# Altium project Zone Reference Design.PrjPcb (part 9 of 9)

## Sheet Class-D Amp.SchDoc
size 431 x 279 mm; Date: Not shown in title block; ApprovedBy: Not shown in title block; CheckedBy: Not shown in title block; Author: Not shown in title block; CompanyName: Not shown in title block; Engineer: Not shown in title block; Organization: Not shown in title block; Address1: Not shown in title block; Address2: Not shown in title block; Address3: Not shown in title block; Address4: Not shown in title block; DocumentNumber: 1; Revision: Use project parameter SCH_Rev; SheetNumber: 25; SheetTotal: 30; PageSetup: Record=PageOptions¦CenterHorizontal=True¦CenterVertical=True¦PrintScale=1.00¦XCorrection=1.00¦YCorrection=1.00¦PrintKind=0¦BorderSize=5000000¦LeftOffset=0¦BottomOffset=0¦Orientation=2¦PaperLength=1000¦PaperWidth=1000¦Scale=100¦PaperSource=15¦PrintQuality=600¦MediaType=1¦DitherType=10¦PaperKind=Letter¦PrintScaleMode=1
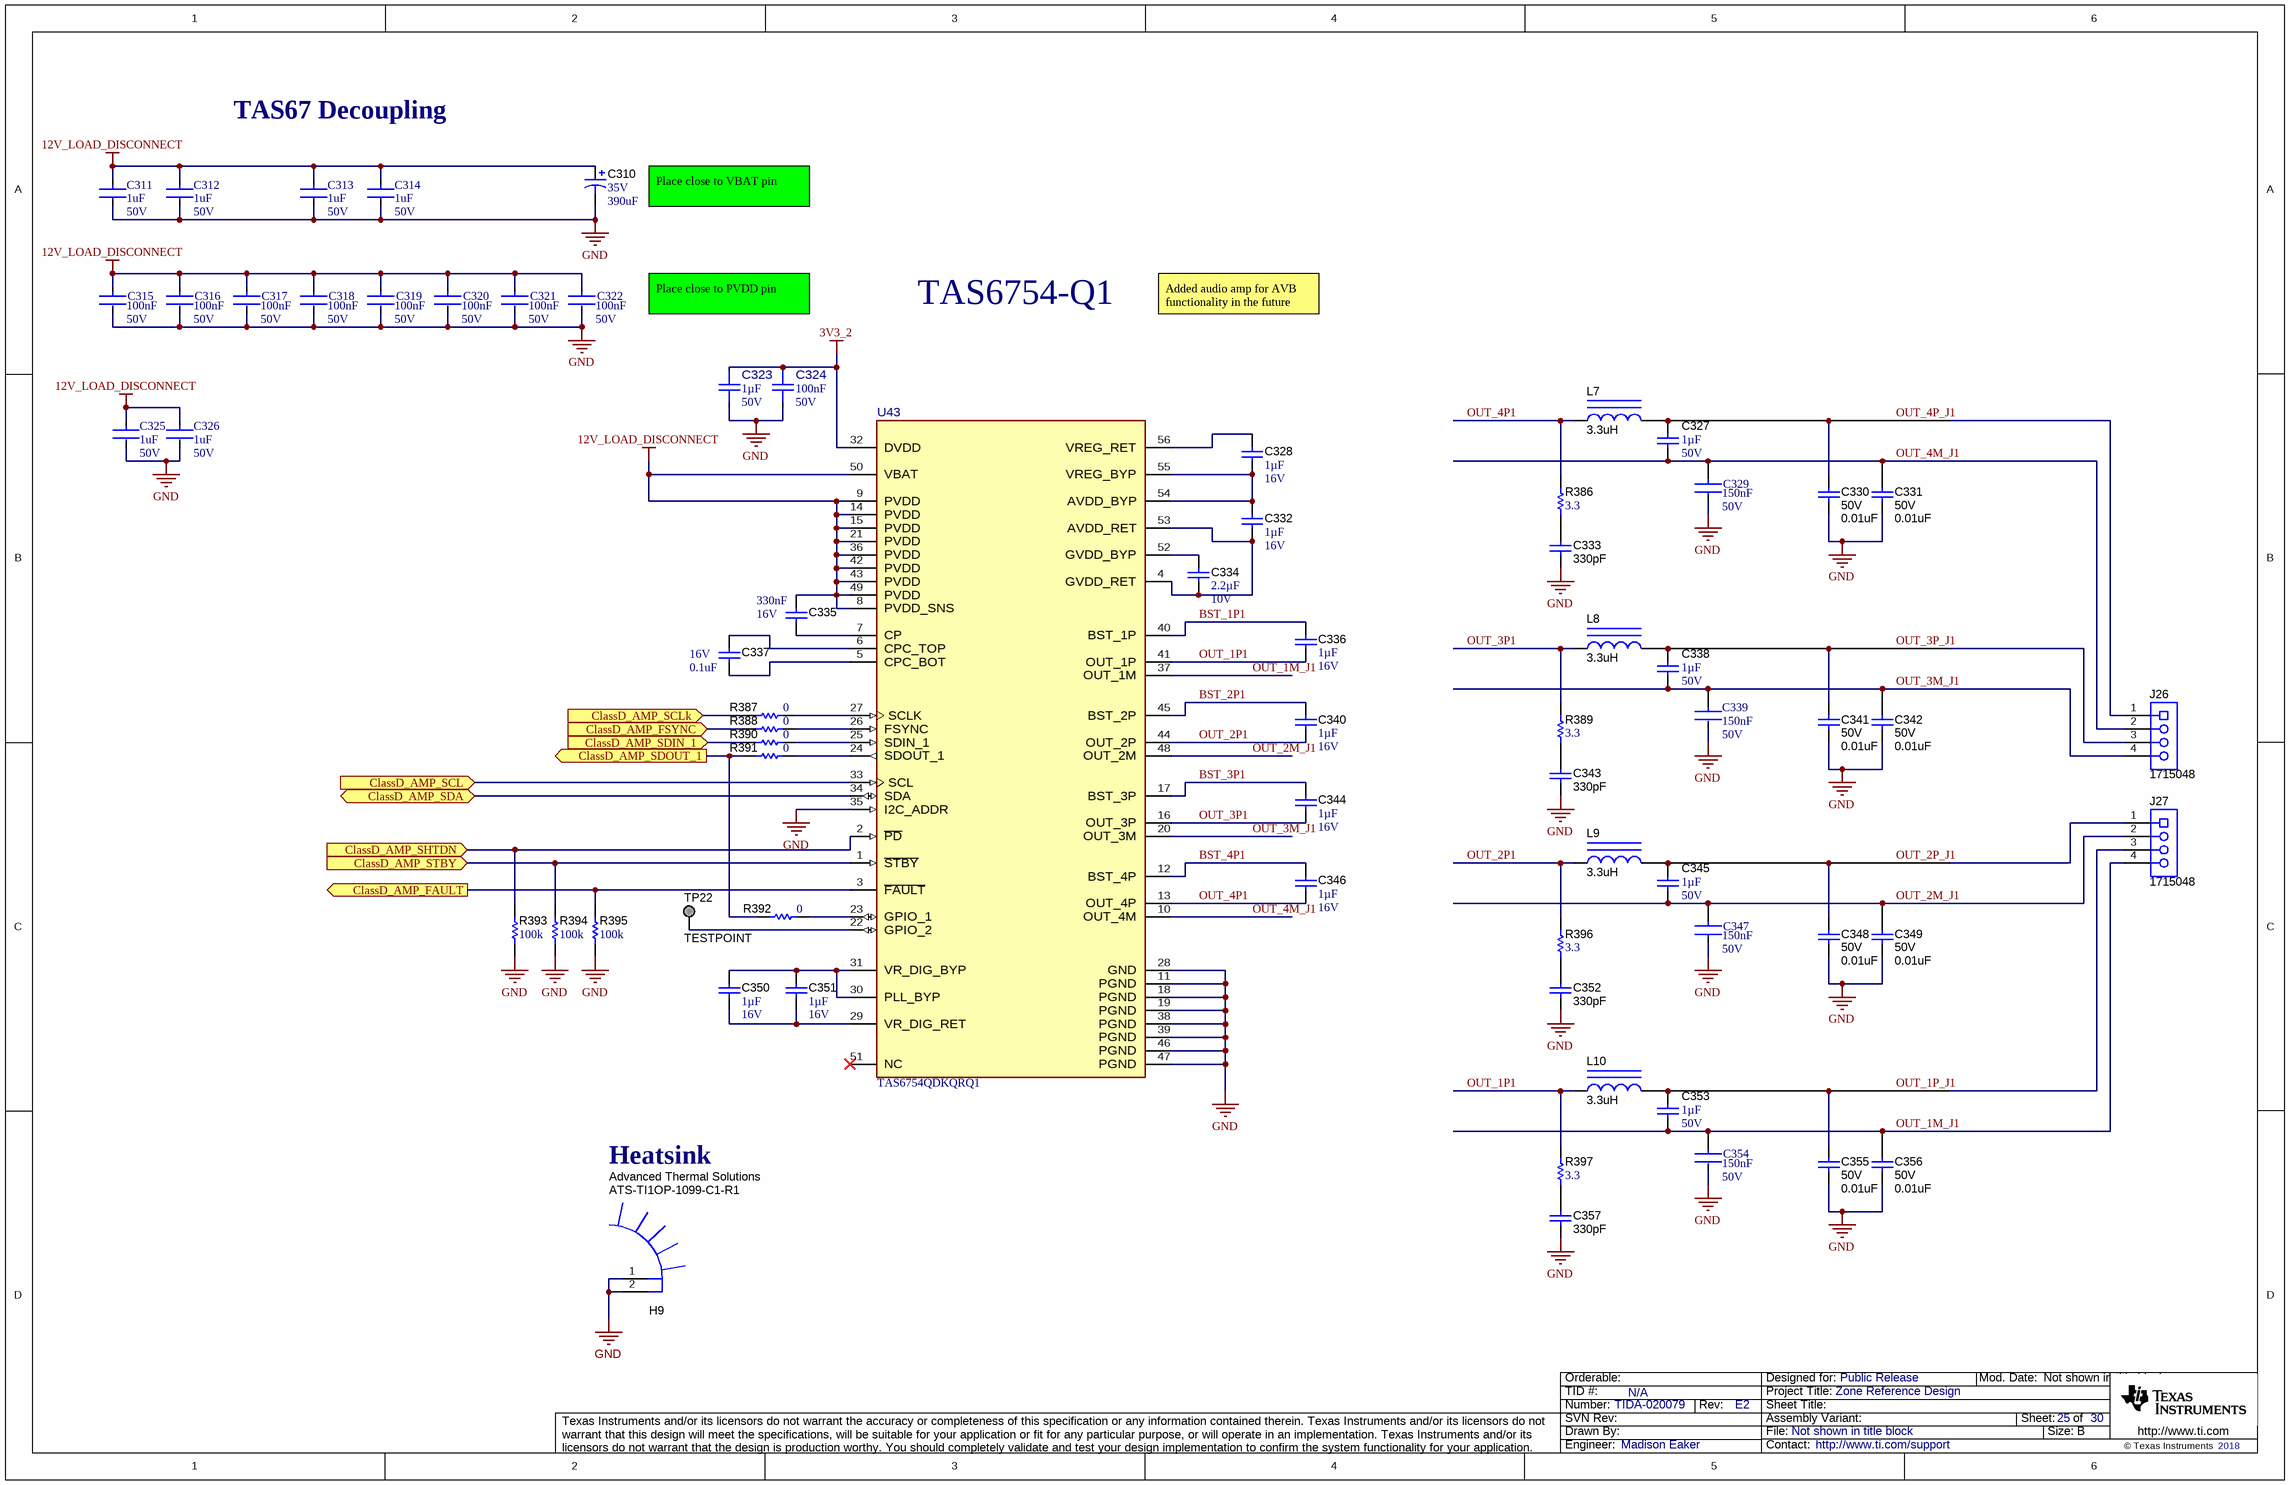
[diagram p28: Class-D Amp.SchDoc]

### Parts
C310  VDC_V: 35V  ValueDisplayed: 390uF  [SM_RADIAL_10BMM]  (hidden comment: UCL1V391MNL1GS)
C311  Voltage Rating: 50V  Capacitance: 1uF  [FP-GCJ21B-0_3-IPC_A]  (hidden comment: GCJ21BR71H105MA01L)
C312  Voltage Rating: 50V  Capacitance: 1uF  [FP-GCJ21B-0_3-IPC_A]  (hidden comment: GCJ21BR71H105MA01L)
C313  Voltage Rating: 50V  Capacitance: 1uF  [FP-GCJ21B-0_3-IPC_A]  (hidden comment: GCJ21BR71H105MA01L)
C314  Voltage Rating: 50V  Capacitance: 1uF  [FP-GCJ21B-0_3-IPC_A]  (hidden comment: GCJ21BR71H105MA01L)
C315  Voltage Rating (DC): 50V  Capacitance: 100nF  [FP-GCJ188-0_2-IPC_C]  (hidden comment: GCJ188R71H104KA12D)
C316  Voltage Rating (DC): 50V  Capacitance: 100nF  [FP-GCJ188-0_2-IPC_C]  (hidden comment: GCJ188R71H104KA12D)
C317  Voltage Rating (DC): 50V  Capacitance: 100nF  [FP-GCJ188-0_2-IPC_C]  (hidden comment: GCJ188R71H104KA12D)
C318  Voltage Rating (DC): 50V  Capacitance: 100nF  [FP-GCJ188-0_2-IPC_C]  (hidden comment: GCJ188R71H104KA12D)
C319  Voltage Rating (DC): 50V  Capacitance: 100nF  [FP-GCJ188-0_2-IPC_C]  (hidden comment: GCJ188R71H104KA12D)
C320  Voltage Rating (DC): 50V  Capacitance: 100nF  [FP-GCJ188-0_2-IPC_C]  (hidden comment: GCJ188R71H104KA12D)
C321  Voltage Rating (DC): 50V  Capacitance: 100nF  [FP-GCJ188-0_2-IPC_C]  (hidden comment: GCJ188R71H104KA12D)
C322  Voltage Rating (DC): 50V  Capacitance: 100nF  [FP-GCJ188-0_2-IPC_C]  (hidden comment: GCJ188R71H104KA12D)
C323  Cap_F: 1µF  VDC_V: 50V  [FP-CL10B105KB9VPJC_0603-MFG]  (hidden comment: CL10B105KB9VPJC)
C324  Cap_F: 100nF  VDC_V: 50V  [FP-C0603X104K5RACAUTO_0603-MFG]  (hidden comment: C0603X104K5RACAUTO)
C325  Voltage Rating: 50V  Capacitance: 1uF  [FP-GCJ21B-0_3-IPC_A]  (hidden comment: GCJ21BR71H105MA01L)
C326  Voltage Rating: 50V  Capacitance: 1uF  [FP-GCJ21B-0_3-IPC_A]  (hidden comment: GCJ21BR71H105MA01L)
C327  Cap_F: 1µF  VDC_V: 50V  [0805_HV]  (hidden comment: GCM21BR71H105KA03K)
C328  Cap_F: 1µF  VDC_V: 16V  [0603]  (hidden comment: GCM188R71C105KA64J)
C329  Voltage Rating: 50V  Capacitance: 150nF  [FP-GCM188-0_1-IPC_C]  (hidden comment: GCM188R71H154KA64D)
C330  VDC_V: 50V  ValueDisplayed: 0.01uF  [0603]  (hidden comment: GRM1885C1H103JA01D)
C331  VDC_V: 50V  ValueDisplayed: 0.01uF  [0603]  (hidden comment: GRM1885C1H103JA01D)
C332  Cap_F: 1µF  VDC_V: 16V  [0603]  (hidden comment: GCM188R71C105KA64J)
C333  ValueDisplayed: 330pF  [0402]  (hidden comment: GRM155R71H331KA01D)
C334  Cap_F: 2.2µF  VDC_V: 10V  [0603]  (hidden comment: GRM188R71A225KE15J)
C335  Cap_F: 330nF  VDC_V: 16V  [0603]  (hidden comment: GRM188R71C334KA01D)
C336  Cap_F: 1µF  VDC_V: 16V  [0603]  (hidden comment: GCM188R71C105KA64D)
C337  VDC_V: 16V  ValueDisplayed: 0.1uF  [0402]  (hidden comment: GCM155R71C104KA55D)
C338  Cap_F: 1µF  VDC_V: 50V  [0805_HV]  (hidden comment: GCM21BR71H105KA03K)
C339  Voltage Rating: 50V  Capacitance: 150nF  [FP-GCM188-0_1-IPC_C]  (hidden comment: GCM188R71H154KA64D)
C340  Cap_F: 1µF  VDC_V: 16V  [0603]  (hidden comment: GCM188R71C105KA64D)
C341  VDC_V: 50V  ValueDisplayed: 0.01uF  [0603]  (hidden comment: GRM1885C1H103JA01D)
C342  VDC_V: 50V  ValueDisplayed: 0.01uF  [0603]  (hidden comment: GRM1885C1H103JA01D)
C343  ValueDisplayed: 330pF  [0402]  (hidden comment: GRM155R71H331KA01D)
C344  Cap_F: 1µF  VDC_V: 16V  [0603]  (hidden comment: GCM188R71C105KA64D)
C345  Cap_F: 1µF  VDC_V: 50V  [0805_HV]  (hidden comment: GCM21BR71H105KA03K)
C346  Cap_F: 1µF  VDC_V: 16V  [0603]  (hidden comment: GCM188R71C105KA64D)
C347  Voltage Rating: 50V  Capacitance: 150nF  [FP-GCM188-0_1-IPC_C]  (hidden comment: GCM188R71H154KA64D)
C348  VDC_V: 50V  ValueDisplayed: 0.01uF  [0603]  (hidden comment: GRM1885C1H103JA01D)
C349  VDC_V: 50V  ValueDisplayed: 0.01uF  [0603]  (hidden comment: GRM1885C1H103JA01D)
C350  Cap_F: 1µF  VDC_V: 16V  [0603]  (hidden comment: GCM188R71C105KA64J)
C351  Cap_F: 1µF  VDC_V: 16V  [0603]  (hidden comment: GCM188R71C105KA64J)
C352  ValueDisplayed: 330pF  [0402]  (hidden comment: GRM155R71H331KA01D)
C353  Cap_F: 1µF  VDC_V: 50V  [0805_HV]  (hidden comment: GCM21BR71H105KA03K)
C354  Voltage Rating: 50V  Capacitance: 150nF  [FP-GCM188-0_1-IPC_C]  (hidden comment: GCM188R71H154KA64D)
C355  VDC_V: 50V  ValueDisplayed: 0.01uF  [0603]  (hidden comment: GRM1885C1H103JA01D)
C356  VDC_V: 50V  ValueDisplayed: 0.01uF  [0603]  (hidden comment: GRM1885C1H103JA01D)
C357  ValueDisplayed: 330pF  [0402]  (hidden comment: GRM155R71H331KA01D)
H9  Manufacturer: Advanced Thermal Solutions  PartNumber: ATS-TI1OP-1099-C1-R1  [HEATSINK-DKQ56_20MMX41_4X32_77MM]  (hidden comment: HeatSink_2)
J26  1715048  [Phoenix_1715048]
J27  1715048  [Phoenix_1715048]
L7  ValueDisplayed: 3.3uH  [VCMT053T]  (hidden comment: VCMT053T-3R3MN5)
L8  ValueDisplayed: 3.3uH  [VCMT053T]  (hidden comment: VCMT053T-3R3MN5)
L9  ValueDisplayed: 3.3uH  [VCMT053T]  (hidden comment: VCMT053T-3R3MN5)
L10  ValueDisplayed: 3.3uH  [VCMT053T]  (hidden comment: VCMT053T-3R3MN5)
R386  ValueDisplayed: 3.3  [0603]  (hidden comment: CRCW06033R30JNEA)
R387  ValueDisplayed: 0  [0603]  (hidden comment: RC0603JR-070RL)
R388  ValueDisplayed: 0  [0603]  (hidden comment: RC0603JR-070RL)
R389  ValueDisplayed: 3.3  [0603]  (hidden comment: CRCW06033R30JNEA)
R390  ValueDisplayed: 0  [0603]  (hidden comment: RC0603JR-070RL)
R391  ValueDisplayed: 0  [0603]  (hidden comment: RC0603JR-070RL)
R392  ValueDisplayed: 0  [0603]  (hidden comment: RC0603JR-070RL)
R393  ValueDisplayed: 100k  [0603]  (hidden comment: CRCW0603100KJNEAC)
R394  ValueDisplayed: 100k  [0603]  (hidden comment: CRCW0603100KJNEAC)
R395  ValueDisplayed: 100k  [0603]  (hidden comment: CRCW0603100KJNEAC)
R396  ValueDisplayed: 3.3  [0603]  (hidden comment: CRCW06033R30JNEA)
R397  ValueDisplayed: 3.3  [0603]  (hidden comment: CRCW06033R30JNEA)
TP22  TESTPOINT  [TP_25MIL-SMT]  (no BOM)
U43  TAS6754QDKQRQ1  [DKQ0056D-MFG]

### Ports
ClassD_AMP_FAULT (out), ClassD_AMP_FSYNC (in), ClassD_AMP_SCL (in), ClassD_AMP_SCLk (in), ClassD_AMP_SDA (bidir), ClassD_AMP_SDIN_1 (in), ClassD_AMP_SDOUT_1 (out), ClassD_AMP_SHTDN (in), ClassD_AMP_STBY (in)

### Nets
3V3_2: C323.1 C324.1 U43.32(DVDD)
12V_LOAD_DISCONNECT: C310.1(+) C311.1 C312.1 C313.1 C314.1 C315.2 C316.2 C317.2 C318.2 C319.2 C320.2 C321.2 C322.2 C325.1 C326.1 C335.2 U43.8(PVDD_SNS) U43.9(PVDD) U43.14(PVDD) U43.15(PVDD) U43.21(PVDD) U43.36(PVDD) U43.42(PVDD) U43.43(PVDD) U43.49(PVDD) U43.50(VBAT)  [project net VS]
GND: C310.2(-) C311.2 C312.2 C313.2 C314.2 C315.1 C316.1 C317.1 C318.1 C319.1 C320.1 C321.1 C322.1 C323.2 C324.2 C325.2 C326.2 C329.2 C330.2 C331.2 C333.1 C339.2 C341.2 C342.2 C343.1 C347.2 C348.2 C349.2 C352.1 C354.2 C355.2 C356.2 C357.1 H9.1 H9.2 R393.2 R394.2 R395.2 U43.11(PGND) U43.18(PGND) U43.19(PGND) U43.28(GND) U43.35(I2C_ADDR) U43.38(PGND) U43.39(PGND) U43.46(PGND) U43.47(PGND)
BST_1P1: C336.2 U43.40(BST_1P)  [project net BST_1P1_25]
BST_2P1: C340.2 U43.45(BST_2P)  [project net BST_2P1_25]
BST_3P1: C344.2 U43.17(BST_3P)  [project net BST_3P1_25]
BST_4P1: C346.2 U43.12(BST_4P)  [project net BST_4P1_25]
ClassD_AMP_FAULT: R395.1 U43.3(~{FAULT}) ; port ClassD_AMP_FAULT
ClassD_AMP_FSYNC: R388.1 ; port ClassD_AMP_FSYNC
ClassD_AMP_SCLk: R387.1 ; port ClassD_AMP_SCLk
ClassD_AMP_SDIN_1: R390.1 ; port ClassD_AMP_SDIN_1
ClassD_AMP_SDOUT_1: R391.1 R392.1 ; port ClassD_AMP_SDOUT_1
ClassD_AMP_SHTDN: R393.1 U43.2(~{PD}) ; port ClassD_AMP_SHTDN
ClassD_AMP_STBY: R394.1 U43.1(~{STBY}) ; port ClassD_AMP_STBY
I2C0_SCL: U43.33(SCL) ; port ClassD_AMP_SCL
I2C0_SDA: U43.34(SDA) ; port ClassD_AMP_SDA
OUT_1M_J1: C353.2 C354.1 C356.1 J27.4 U43.37(OUT_1M)  [project net OUT_1M_J1_25]
OUT_1P1: C336.1 L10.1 R397.2 U43.41(OUT_1P)  [project net OUT_1P1_25]
OUT_1P_J1: C353.1 C355.1 J27.3 L10.2  [project net OUT_1P_J1_25]
OUT_2M_J1: C345.2 C347.1 C349.1 J27.2 U43.48(OUT_2M)  [project net OUT_2M_J1_25]
OUT_2P1: C340.1 L9.1 R396.2 U43.44(OUT_2P)  [project net OUT_2P1_25]
OUT_2P_J1: C345.1 C348.1 J27.1 L9.2  [project net OUT_2P_J1_25]
OUT_3M_J1: C338.2 C339.1 C342.1 J26.4 U43.20(OUT_3M)  [project net OUT_3M_J1_25]
OUT_3P1: C344.1 L8.1 R389.2 U43.16(OUT_3P)  [project net OUT_3P1_25]
OUT_3P_J1: C338.1 C341.1 J26.3 L8.2  [project net OUT_3P_J1_25]
OUT_4M_J1: C327.2 C329.1 C331.1 J26.2 U43.10(OUT_4M)  [project net OUT_4M_J1_25]
OUT_4P1: C346.1 L7.1 R386.2 U43.13(OUT_4P)  [project net OUT_4P1_25]
OUT_4P_J1: C327.1 C330.1 J26.1 L7.2  [project net OUT_4P_J1_25]
NetC328_1: C328.1 C332.2 U43.54(AVDD_BYP) U43.55(VREG_BYP)
NetC328_2: C328.2 U43.56(VREG_RET)
NetC332_1: C332.1 C334.1 U43.4(GVDD_RET) U43.53(AVDD_RET)
NetC333_2: C333.2 R386.1
NetC334_2: C334.2 U43.52(GVDD_BYP)
NetC335_1: C335.1 U43.7(CP)
NetC337_1: C337.1 U43.6(CPC_TOP)
NetC337_2: C337.2 U43.5(CPC_BOT)
NetC343_2: C343.2 R389.1
NetC350_1: C350.1 C351.1 U43.29(VR_DIG_RET)
NetC350_2: C350.2 C351.2 U43.30(PLL_BYP) U43.31(VR_DIG_BYP)
NetC352_2: C352.2 R396.1
NetC357_2: C357.2 R397.1
NetR387_2: R387.2 U43.27(SCLK)
NetR388_2: R388.2 U43.26(FSYNC)
NetR390_2: R390.2 U43.25(SDIN_1)
NetR391_2: R391.2 U43.24(SDOUT_1)
NetR392_2: R392.2 U43.23(GPIO_1)
NetTP22_1: TP22.1 U43.22(GPIO_2)

Not connected (* = marked no-connect by the designer): U43 51(NC)*

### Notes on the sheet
- TAS67 Decoupling
- Place close to VBAT pin
- Place close to PVDD pin
- TAS6754-Q1
- Added audio amp for AVB functionality in the future
- Heatsink

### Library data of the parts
C310 = CMP-0011092-1: CAP, AL, 390 uF, 35 V, +/- 20%, 0.08 ohm, SMD; Manufacturer: Nichicon; TaMin_C: -55°C; ESR_ohm: 80m; Polarized: Y; SizeAreaWB_mm2: 159.9; U/M: EA; Value: 390uF; TaMax_C: 105°C; SizeZ_mm: 10.2; SizeX_mm: 11; SizeY_mm: 10.3; Cap_Case: 10x10; SizeArea_mm2: 113.3; CompType: Capacitor; Cap_F: 390µF; IRMS_A: 850mA; AEC Category: Q200
C311-C314 C325 C326 = CMP-06035-059042-1: Multilayer Ceramic Capacitors MLCC - SMD/SMT 0805 1uF 20%, 50VDC,  X7R 15%
C315-C322 = CMP-2006-02223-2: Cap Ceramic 0.1uF 50V X7R 10% Pad SMD 0603 Soft Termination +125°C Automotive T/R
C323 = CMP-0122257-1: 1 µF ±10% 50V Ceramic Capacitor X7R 0603 (1608 Metric); Manufacturer: Samsung; AEC Grade: Grade 1; AEC Qualified: Yes; SizeZ_mm: 1mm; TempCo: 15%; ValueDisplayed: 1uF; Value: 1µF
C324 = CMP-0122397-1: Cap Ceramic 0.1uF 50V X7R 10% Pad SMD 0603 Flexible Termination 125C Automotive T/R; Manufacturer: Kemet; AEC Grade: Grade 1; AEC Qualified: Yes; SizeZ_mm: 0.95mm; TempCo: 15%; Value: 100nF
C327 C338 C345 C353 = CMP-0086249-1: CAP, CERM, 1 µF, 50 V,+/- 10%, X7R, AEC-Q200 Grade 1, 0805; Manufacturer: MuRata; Value: 1uF; AEC Qualified: Y; AEC Category: Q200; U/M: EA; AEC Grade: 1; SizeArea_mm2: 2.5; SizeAreaWB_mm2: 6.75; SizeZ_mm: 1.45; SizeX_mm: 2; Cap_Case: 0805; TaMax_C: 125°C; Polarized: N; SizeY_mm: 1.25; TaMin_C: -55°C
C328 C332 C350 C351 = CMP-0079154-1: CAP, CERM, 1 µF, 16 V,+/- 10%, X7R, AEC-Q200 Grade 1, 0603; Manufacturer: MuRata; SizeAreaWB_mm2: 4.68; SizeArea_mm2: 1.28; AEC Qualified: Y; AEC Category: Q200; Value: 1uF; TaMax_C: 125°C; SizeZ_mm: 1; Polarized: N; TaMin_C: -55°C; SizeY_mm: 0.8; U/M: EA; SizeX_mm: 1.6
C329 C339 C347 C354 = CMP-2006-02379-2: Ceramic Capacitor for Automotive 150nF  ±10% 50VDC X7R 0603 Paper T/R
C330 C331 C341 C342 C348 C349 C355 C356 = CMP-0007174-3: CAP, CERM, 0.01 uF, 50 V, +/- 5%, C0G/NP0, 0603; Manufacturer: MuRata; TaMin_C: -55°C; Polarized: N; SizeAreaWB_mm2: 4.68; Value1: Unknown; U/M: EA; Value: 0.01uF; TaMax_C: 125°C; SizeZ_mm: 1; SizeX_mm: 1.6; SizeY_mm: 0.8; SizeArea_mm2: 1.28; Cap_F: 10nF; AEC Category: Q200
C333 C343 C352 C357 = CMP-0006687-1: CAP, CERM, 330 pF, 50 V, +/- 10%, X7R, 0402; Manufacturer: MuRata; TaMin_C: -55°C; Polarized: N; SizeAreaWB_mm2: 3; Value1: Unknown; U/M: EA; Value: 330pF; TaMax_C: 125°C; SizeZ_mm: 0.6; SizeX_mm: 1; SizeY_mm: 0.5; Value2: 50V; AEC Category: Q200
C334 = CMP-0084284-1: CAP, CERM, 2.2 µF, 10 V,+/- 10%, X7R, AEC-Q200 Grade 1, 0603; Manufacturer: MuRata; SizeAreaWB_mm2: 4.68; Polarized: N; AEC Qualified: Y; SizeX_mm: 1.6; SizeZ_mm: 1; SizeY_mm: 0.8; U/M: EA; TaMin_C: -55°C; Value: 2.2uF; AEC Category: Q200; TaMax_C: 125°C; SizeArea_mm2: 1.28
C335 = CMP-0007393-2: CAP, CERM, 0.33 uF, 16 V, +/- 10%, X7R, 0603; Manufacturer: MuRata; TaMin_C: -55°C; Polarized: N; SizeAreaWB_mm2: 4.68; Value1: Unknown; U/M: EA; Value: 0.33uF; TaMax_C: 125°C; SizeZ_mm: 1; SizeX_mm: 1.6; SizeY_mm: 0.8; SizeArea_mm2: 1.28; AEC Category: Q200
C336 C340 C344 C346 = CMP-0007136-1: CAP, CERM, 1 uF, 16 V, +/- 10%, X7R, AEC-Q200 Grade 1, 0603; Manufacturer: MuRata; TaMin_C: -55°C; Polarized: N; SizeAreaWB_mm2: 4.68; Value1: Unknown; U/M: EA; Value: 1uF; TaMax_C: 125°C; SizeZ_mm: 1; SizeX_mm: 1.6; SizeY_mm: 0.8; SizeArea_mm2: 1.28; AEC Qualified: Y; AEC Category: Q200
C337 = CMP-0006351-1: CAP, CERM, 0.1 uF, 16 V, +/- 10%, X7R, 0402; Manufacturer: MuRata; TaMin_C: -55°C; Polarized: N; SizeAreaWB_mm2: 3; Value1: Unknown; U/M: EA; Value: 0.1uF; TaMax_C: 125°C; SizeZ_mm: 0.6; SizeX_mm: 1; SizeY_mm: 0.5; Cap_F: 100nF; AEC Category: Q200
H9 = CMP-0004050-1: Heat Sink for DKQ Packages, 41.4x20 mm; Key: HS-DKQ56_20X41.4X32.77
J26 J27 = CMP-0055526-1: Terminal Block, 5mm, 4x1, R/A,TH; Manufacturer: Phoenix Contact; Cert_VDE: Y; CNHeader: FALSE; Current_A: 17.5A; Gender: Female; Voltage_V: 400V; Row_Count: 1; Pitch_mm: 5; CT: TRUE
L7-L10 = CMP-0059924-1: Inductor, 3.3 uH, 4.5 A, 0.038 ohm, AEC-Q200 Grade 0, SMD; Manufacturer: Cyntec; Isat: 4.5A @ 30% inductance drop; Irms: 5A @ 40C rise; SizeAreaWB_mm2: 54.0125; DCR_ohm: 0.038; Value: 3.3uH; Imax_A: 4.5A; SizeZ_mm: 3; SizeX_mm: 5.45; SizeY_mm: 5.25; SizeArea_mm2: 28.6125; Ind_H: 3.3µH; AEC Qualified: Y; AEC Grade: 0; AEC Category: Q200
R386 R389 R396 R397 = CMP-0025805-4: RES, 3.3, 5%, 0.1 W, AEC-Q200 Grade 0, 0603; Manufacturer: Vishay-Dale; Power_W: 100mW; TempCo: 200 ppm/C; Value_Code: 3R30; Value: 3.3; EIA_Code: E24; SizeX_mm: 1.6; SizeY_mm: 0.8; SizeZ_mm: 1; Value2: 0.1W; SizeArea_mm2: 1.28; AEC Qualified: Y; VDC_V: 75V; AEC Category: Q200; AEC Grade: 0
R387 R388 R390-R392 = CMP-0025885-5: RES, 0, 5%, 0.1 W, 0603; Manufacturer: Yageo; Power_W: 100mW; TempCo: 200 ppm/C; Value_Code: 0000; Value: 0; EIA_Code: E24; SizeX_mm: 1.6; SizeZ_mm: 1; Value2: 0.1W; SizeArea_mm2: 1.28; AEC Qualified: N; VDC_V: 75V; AEC Category: Q200; SizeY_mm: 0.8; SizeAreaWB_mm2: 4.68
R393-R395 = CMP-0082530-1: RES, 100 k, 5%, 0.1 W, 0603; Manufacturer: Vishay-Dale; Power_W: 100mW; TempCo: 200 ppm/C; SizeAreaWB_mm2: 4.68; Value: 100k; EIA_Code: E24; SizeX_mm: 1.6; SizeY_mm: 0.8; SizeZ_mm: 1; Value2: 0.1W; SizeArea_mm2: 1.28; AEC Qualified: N; VDC_V: 75V; AEC Category: Q200
TP22 = CMP-0078143-3: TEST POINT.  No entry in BOM.
U43 = CMP-0123170-1: 1L Modulation, 2-MHz Digital Input 4-Channel Automotive Class-D Audio Amplifier with Current Sense and Real-time Load Diagnostics; Manufacturer: Texas Instruments; Part Number: TAS6764QDKQRQ1; SizeZ_mm: 2.475mm; AEC Qualified: Yes; AEC Grade: Grade 1; Max Supply Voltage: 26.4V; Min Supply Voltage: 4.5V; Nominal Supply Current: 40-81mA; Number Of Channels: 4; Power At Speaker R: 75W @ 4Ω; Standoff Height: 0mm; TaMax_C: +125°C; TaMin_C: -40°C; TJmax_C: +175°C

## Sheet Zone Reference Design_Hardware.SchDoc
size 431 x 279 mm; Date: Not shown in title block; ApprovedBy: Not shown in title block; CheckedBy: Not shown in title block; Author: Not shown in title block; CompanyName: Not shown in title block; Engineer: Not shown in title block; Organization: Not shown in title block; Address1: Not shown in title block; Address2: Not shown in title block; Address3: Not shown in title block; Address4: Not shown in title block; DocumentNumber: 1; Revision: Use project parameter SCH_Rev; SheetNumber: 30; SheetTotal: 30; PageSetup: Record=PageOptions¦CenterHorizontal=True¦CenterVertical=True¦PrintScale=1.00¦XCorrection=1.00¦YCorrection=1.00¦PrintKind=0¦BorderSize=5000000¦LeftOffset=0¦BottomOffset=0¦Orientation=2¦PaperLength=1000¦PaperWidth=1000¦Scale=100¦PaperSource=15¦PrintQuality=600¦MediaType=1¦DitherType=10¦PaperKind=Letter¦PrintScaleMode=1
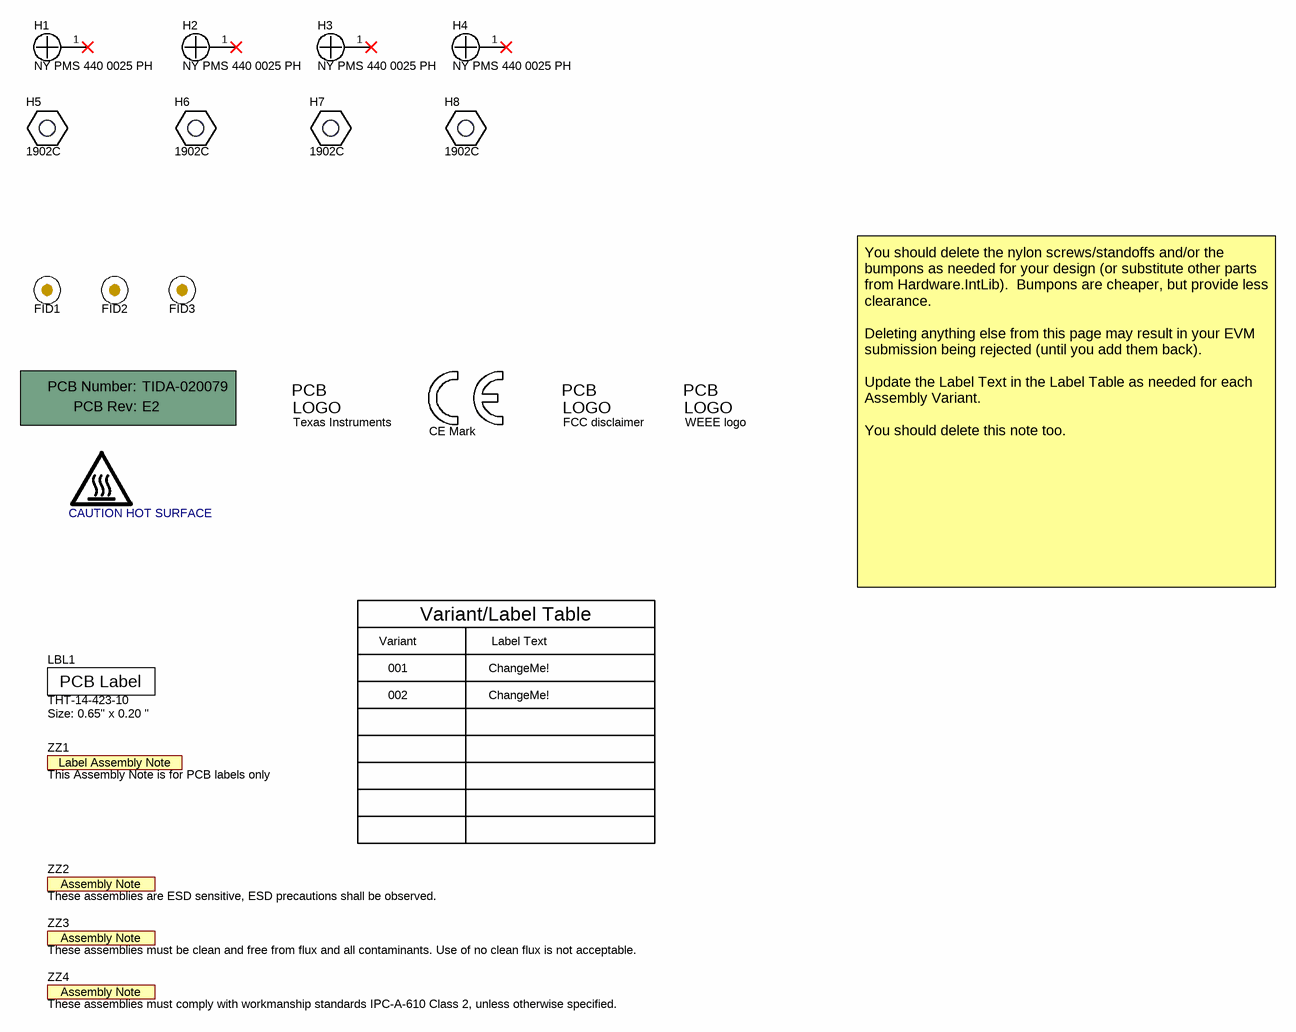
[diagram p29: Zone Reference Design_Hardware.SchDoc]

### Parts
!PCB1  Printed Circuit Board  (value not drawn)  (mechanical)
FID1  Fiducial  [Fiducial10-20]  (value not drawn)
FID2  Fiducial  [Fiducial10-20]  (value not drawn)
FID3  Fiducial  [Fiducial10-20]  (value not drawn)
H1  NY PMS 440 0025 PH  [NY PMS 440 0025 PH]
H2  NY PMS 440 0025 PH  [NY PMS 440 0025 PH]
H3  NY PMS 440 0025 PH  [NY PMS 440 0025 PH]
H4  NY PMS 440 0025 PH  [NY PMS 440 0025 PH]
H5  1902C  [Keystone_1902C]
H6  1902C  [Keystone_1902C]
H7  1902C  [Keystone_1902C]
H8  1902C  [Keystone_1902C]
LBL1  THT-14-423-10  Note: Size: 0.65" x 0.20 "  [Label_650x200]
Logo1  CE Mark  [CE_Mark_5mm]  (no BOM)
Logo2  Texas Instruments  [TI_Stacked_Overlay_Small]  (no BOM)
Logo3  FCC disclaimer  [FCC_disclaimer]  (no BOM)
Logo4  WEEE logo  [WEEE_Minimum]  (no BOM)
LOGO5  CAUTION HOT SURFACE  [IEC_HotSurface_Medium]  (no BOM)
ZZ1  This Assembly Note is for PCB labels only  [AssemblyNoteLabel]  (no BOM)
ZZ2  These assemblies are ESD sensitive, ESD precautions shall be observed.  [AssemblyNote]  (no BOM)
ZZ3  These assemblies must be clean and free from flux and all contaminants. Use of no clean flux is not acceptable.  [AssemblyNote]  (no BOM)
ZZ4  These assemblies must comply with workmanship standards IPC-A-610 Class 2, unless otherwise specified.  [AssemblyNote]  (no BOM)

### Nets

Not connected (* = marked no-connect by the designer): H1 1*; H2 1*; H3 1*; H4 1*

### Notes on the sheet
- Variant
- Variant/Label Table
- Label Text
- You should delete the nylon screws/standoffs and/or the bumpons as needed for your design (or substitute other parts from Hardware.IntLib).  Bumpons are cheaper, but provide less clearance.
  Deleting anything else from this page may result in your EVM submission being rejected (until you add them back).
  Update the Label Text in the Label Table as needed for each Assembly Variant.
  You should delete this note too.
- 001
- 002
- ChangeMe!

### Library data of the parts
!PCB1 = CMP-0003618-2: Manufacturer: Any; PartNumber: TIDA-020079
FID1-FID3 = CMP-0077181-1: Fiducial mark.  There is nothing to buy or mount.
H1-H4 = CMP-0003617-1: Machine Screw, Round, #4-40 x 1/4, Nylon, Philips panhead; Manufacturer: B&F Fastener Supply; CompType: Hardware
H5-H8 = CMP-0003610-1: Standoff, Hex, 0.5"L #4-40 Nylon; Manufacturer: Keystone; CompType: Hardware
LBL1 = CMP-0003625-1: Thermal Transfer Printable Labels, 0.650" W x 0.200" H - 10,000 per roll; Manufacturer: Brady; CompType: Label
Logo1 = CMP-0074844-1: SymbolCreator: a0412235
Logo2 = CMP-0074838-1: Texas Instrument Corporate Signature; SymbolCreator: a0412235; Lib Reference: TI_Logo; Library Reference: Logo
Logo3 = CMP-0074847-1: FCC_disclaimer; Library Reference: Logo
Logo4 = CMP-0074769-1
LOGO5 = CMP-0074837-1: IEC 61010-1 Hot Surface Warning; SymbolCreator: a0412235
ZZ1 = CMP-0003616-3
ZZ2 = CMP-0077236-1
ZZ3 = CMP-0077237-1
ZZ4 = CMP-0077238-1

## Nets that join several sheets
1V1: Power Overview (R358.1), PMIC (J14.9), BUCKs and LDO (C371.1 L12.2 R414.2 U47.3), Ethernet (6 pins)
1V2: BUCKs and LDO (5 pins), AM263P Power Caps (48 pins)
1V8: Power Overview (R357.1), PMIC (5 pins), BUCKs and LDO (C368.1 U46.5), AM263P ADC (S1.3 S1.6)
3V3_1: Power Overview (5 pins), Input Supply (R25.2 R26.2 R27.2 U3.1), PMIC (6 pins), BUCKs and LDO (R401.2 R412.2), Load Driver Overview (R1.2 R2.2 R3.2), High Side Switches (R119.2 R123.2 R135.2), TPS1211-Q1 (R378.1 R380.1), Smart Fuse HSS (R90.1 R107.1), CAN-LIN Overview (R384.2), LIN (5 pins), MUXes and TPLD (12 pins), IO Expanders (5 pins), AM263P Overview (J20.1), AM263P Reset Circuit (13 pins), AM263P Power Caps (20 pins), AM263P Temp and EEPROM (6 pins), AM263P OSPI Bootmode (32 pins), AM263P PRU_EPWM (R221.2 R222.2)
3V3_2: Power Overview (R351.1 R354.1 R355.1), PMIC (C290.1 C291.1 J14.7 U41.11), DRV8714S-Q1 (6 pins), DRV8x45S-Q1 and DRV81242-Q1 (6 pins), CAN1 (C19.1 C24.1 U5.5 U6.5), CAN2 (C30.1 C33.1 U7.11 U8.16), AM263P PRU_EPWM (R238.2 R239.2), Ethernet (44 pins), Class-D Amp (C323.1 C324.1 U43.32)
3V3_ALWAYS_ON: Power Overview (R343.1 R349.1), Input Supply (R35.2), PMIC (J14.10), BUCKs and LDO (Q22.2), High Side Switches (R141.2 R142.2), Smart Fuse HSS (8 pins), TPS1214-Q1 (R464.2 R468.2 R469.2), MUXes and TPLD (7 pins), TIC12400-Q1 (C139.2 R182.1 R185.1 U31.19), IO Expanders (C387.1 R450.1 R451.1 U55.21), Ethernet (J12.30 J12.32 J13.30 J13.32)
5V0_1: Power Overview (R352.2), PMIC (C292.1 C294.1 J14.4 U41.15), CAN-LIN Overview (J24.9), CAN1 (C17.1 C23.1 U5.3 U6.3)
5V0_2: Power Overview (R353.2), PMIC (C298.1 C299.1 J14.5 U41.20), CAN2 (C28.1 U7.3)
5V_TRACK: PMIC (J14.1), BUCKs and LDO (C363.1 C366.1 R407.2 U46.1)
6V0_BB: PMIC (11 pins), BUCKs and LDO (C367.1 C370.1 U45.6 U47.6)
12V_ALWAYS_ON: Input Supply (R30.2 R33.2 TP3.1), PMIC (17 pins), BUCKs and LDO (8 pins), High Side Switches (6 pins), Smart Fuse HSS (13 pins), TPS1214-Q1 (7 pins), LIN (11 pins), CAN1 (C18.1 U5.10), TIC12400-Q1 (C135.2 C136.1 U31.37 U31.38), AM263P Reset Circuit (R324.1), Ethernet (8 pins)
12V_VBATT_1: Input Supply (11 pins), High Side Switches (C89.1 C90.1 U26.2)
GND: Power Overview (29 pins), Input Supply (24 pins), PMIC (46 pins), BUCKs and LDO (36 pins), High Side Switches (34 pins), DRV8714S-Q1 (31 pins), DRV8x45S-Q1 and DRV81242-Q1 (27 pins), TPS1211-Q1 (12 pins), Smart Fuse HSS (24 pins), TPS1214-Q1 (20 pins), CAN-LIN Overview (6 pins), LIN (13 pins), CAN1 (17 pins), CAN2 (15 pins), IO Management (24 pins), MUXes and TPLD (39 pins), TIC12400-Q1 (34 pins), IO Expanders (7 pins), AM263P Overview (10 pins), AM263P Reset Circuit (21 pins), AM263P Power Caps (149 pins), AM263P Temp and EEPROM (8 pins), AM263P OSPI Bootmode (20 pins), AM263P ADC (51 pins), AM263P PRU_EPWM (U32.U1), Ethernet (80 pins), Class-D Amp (47 pins)
VDDA18_LDO: AM263P Power Caps (10 pins), AM263P ADC (C247.2 C248.2 R310.1 U32.T13)
VS: Input Supply (11 pins), High Side Switches (7 pins), DRV8714S-Q1 (29 pins), DRV8x45S-Q1 and DRV81242-Q1 (15 pins), TPS1211-Q1 (7 pins), AM263P Power Caps (R212.2), Class-D Amp (26 pins)
1V2_PG: BUCKs and LDO (R412.1 U45.1), AM263P Reset Circuit (U38.1)
3V3_ADC: BUCKs and LDO (R398.1 R399.2), MUXes and TPLD (U52.2)
3V3_AlwaysOn_Monitor_MCU: MUXes and TPLD (R445.1), AM263P ADC (R298.1)
A0_TMUX1308: MUXes and TPLD (U48.11), AM263P PRU_EPWM (U32.B4)
A1_TMUX1308: MUXes and TPLD (U48.10), AM263P PRU_EPWM (U32.A2)
A2_TMUX1308: MUXes and TPLD (U48.9), AM263P PRU_EPWM (U32.C6)
ADC0_AIN0: Input Supply (R28.1 U1.10), AM263P ADC (R294.1)
ADC0_AIN1: Input Supply (U2.6), AM263P ADC (R296.1)
ADC1_AIN0: MUXes and TPLD (U48.3), AM263P ADC (R300.1)
ADC2_AIN0: Smart Fuse HSS (C73.1 R103.2 U22.3), AM263P ADC (R302.1)
ADC2_AIN1: Smart Fuse HSS (C63.1 R87.2 U20.2), AM263P ADC (R304.1)
ADC2_AIN2: Smart Fuse HSS (C69.1 R96.2 U21.2), AM263P ADC (R306.1)
ADC2_AIN5: TPS1211-Q1 (R381.2 U42.7), AM263P ADC (R314.1)
ADC3_AIN0: High Side Switches (R128.1), AM263P ADC (R301.1)
ADC3_AIN1: High Side Switches (R111.1), AM263P ADC (R303.1)
ADC3_AIN2: High Side Switches (R124.2), AM263P ADC (R305.1)
ADC3_AIN3: High Side Switches (R147.2), AM263P ADC (R307.1)
ADC4_AIN0: DRV8x45S-Q1 and DRV81242-Q1 (C121.2 R169.2 U29.2), AM263P ADC (R309.1)
ADC4_AIN1: DRV8x45S-Q1 and DRV81242-Q1 (C120.2 R168.2 U28.2), AM263P ADC (R311.1)
ADC4_AIN2: DRV8714S-Q1 (U27.12), AM263P ADC (R313.1)
ADC4_AIN3: DRV8714S-Q1 (U27.13), AM263P ADC (R315.1)
BIST_EN_TPS3762: BUCKs and LDO (U44.6), AM263P PRU_EPWM (U32.A15)
BIST_TPS3762: BUCKs and LDO (R401.1 U44.5), AM263P PRU_EPWM (U32.C14)
BRAKE_DRV8714: DRV8714S-Q1 (U27.14), IO Expanders (U54.10)
CAN1_1046_N: CAN-LIN Overview (J25.10), CAN2 (5 pins)
CAN1_1046_P: CAN-LIN Overview (J25.12), CAN2 (5 pins)
CAN2_1046_N: CAN-LIN Overview (J25.6), CAN2 (5 pins)
CAN2_1046_P: CAN-LIN Overview (J25.8), CAN2 (5 pins)
CAN2_RXD: CAN1 (U6.4), AM263P PRU_EPWM (U32.A12)
CAN2_TXD: CAN1 (U6.1), AM263P PRU_EPWM (U32.B12)
CAN5_RXD: CAN2 (U8.14), AM263P PRU_EPWM (U32.C16)
CAN5_TXD: CAN2 (U8.10), AM263P PRU_EPWM (U32.A17)
CAN6_RXD: CAN2 (U8.6), AM263P PRU_EPWM (U32.B18)
CAN6_TXD: CAN2 (U8.3), AM263P PRU_EPWM (U32.B17)
CAN7_RXD: CAN1 (U5.4), AM263P PRU_EPWM (U32.D16)
CAN7_TXD: CAN1 (U5.1), AM263P PRU_EPWM (U32.C17)
CAN_1043_N: CAN-LIN Overview (J23.2 J24.2), CAN1 (5 pins)
CAN_1043_P: CAN-LIN Overview (J23.1 J24.7), CAN1 (5 pins)
CAN_1044_N: CAN-LIN Overview (J25.2), CAN1 (5 pins)
CAN_1044_P: CAN-LIN Overview (J25.4), CAN1 (5 pins)
ClassD_AMP_FAULT: IO Expanders (U54.5), Class-D Amp (R395.1 U43.3)
ClassD_AMP_FSYNC: Ethernet (U17.4), Class-D Amp (R388.1)
ClassD_AMP_SCLk: Ethernet (U14.4), Class-D Amp (R387.1)
ClassD_AMP_SDIN_1: AM263P PRU_EPWM (U32.G18), Class-D Amp (R390.1)
ClassD_AMP_SDOUT_1: AM263P PRU_EPWM (U32.F17), Class-D Amp (R391.1 R392.1)
ClassD_AMP_SHTDN: IO Expanders (U54.6), Class-D Amp (R393.1 U43.2)
ClassD_AMP_STBY: IO Expanders (U54.4), Class-D Amp (R394.1 U43.1)
CRS_DV/RX_CTRL_ETH1: AM263P PRU_EPWM (R245.2), Ethernet (U13.11)
CRS_DV/RX_CTRL_ETH2: AM263P PRU_EPWM (R230.1), Ethernet (U19.11)
CS_IO: IO Expanders (R447.2 U54.28), AM263P Overview (J19.6), AM263P PRU_EPWM (R219.1)
CS_IO_1_MCU: MUXes and TPLD (U51.15), AM263P Overview (J19.5), AM263P PRU_EPWM (U32.F4)
CS_IO_1_MUX: MUXes and TPLD (U51.9), TIC12400-Q1 (R185.2 U31.15)
CS_LD_1: Smart Fuse HSS (R90.2 R91.1), MUXes and TPLD (U51.7)
CS_LD_1_MCU: MUXes and TPLD (U51.17), AM263P Overview (J17.10), AM263P PRU_EPWM (U32.J4)
CS_LD_2: Smart Fuse HSS (R107.2 R108.1), MUXes and TPLD (U51.8)
CS_LD_4: DRV8x45S-Q1 and DRV81242-Q1 (R178.2 R179.1), AM263P Overview (J17.5), AM263P PRU_EPWM (U32.K3)
CS_PMIC: PMIC (R338.2 U41.36), MUXes and TPLD (U52.3)
CS_PMIC_MCU: MUXes and TPLD (U52.21), AM263P Overview (J18.5), AM263P PRU_EPWM (U32.D7)
DI_HCS: Smart Fuse HSS (6 pins), MUXes and TPLD (U51.5)
DI_HCS_MCU: MUXes and TPLD (U51.19), AM263P Reset Circuit (U32.M2)
DIAGEN_TPS1HC04: High Side Switches (R133.1), IO Expanders (U54.18)
DIAGEN_TPS1HC30: High Side Switches (R116.1), IO Expanders (U54.27)
DIAGEN_TPS2HC08: High Side Switches (R117.1), IO Expanders (U54.15)
DIAGEN_TPS4HC120: High Side Switches (R139.1), IO Expanders (U55.14)
DRVOFF_DRV8145: DRV8x45S-Q1 and DRV81242-Q1 (U28.10 U29.11), IO Expanders (U54.8)
EN1_TLIN1024A: LIN (5 pins), AM263P PRU_EPWM (U32.A5)
EN1_TPS2HC08: High Side Switches (R112.1), IO Expanders (U54.12)
EN1_TPS4HC120: High Side Switches (R129.1), IO Expanders (U55.10)
EN2_TPS2HC08: High Side Switches (R115.1), IO Expanders (U54.13)
EN2_TPS4HC120: High Side Switches (R132.1), IO Expanders (U55.11)
EN3_TPS4HC120: High Side Switches (R134.1), IO Expanders (U55.12)
EN4_TPS4HC120: High Side Switches (R136.1), IO Expanders (U55.13)
EN/IN1_DRV8245: DRV8x45S-Q1 and DRV81242-Q1 (U28.11), AM263P PRU_EPWM (R214.1)
EN_ETH: IO Expanders (U55.2), Ethernet (J12.26 J13.26)
EN_INA186: Input Supply (R25.1 U1.6 U3.3), AM263P PRU_EPWM (U32.B10)
EN_TCAN1043A: CAN1 (U5.6), AM263P PRU_EPWM (U32.B16)
EN_TPS1HC04: High Side Switches (R130.1), IO Expanders (U54.17)
EN_TPS1HC30: High Side Switches (R113.1), IO Expanders (U54.21)
EN_TPS1214: TPS1214-Q1 (R464.1 U56.1), IO Expanders (U55.7)
EPWM0_B: DRV8x45S-Q1 and DRV81242-Q1 (U28.12), AM263P PRU_EPWM (R215.1)
EPWM1_A: DRV8x45S-Q1 and DRV81242-Q1 (R173.1), AM263P PRU_EPWM (R216.1)
EPWM1_B: DRV8x45S-Q1 and DRV81242-Q1 (R174.1), AM263P PRU_EPWM (R217.1)
EPWM2_A: DRV8x45S-Q1 and DRV81242-Q1 (U29.12), AM263P PRU_EPWM (R218.1)
EPWM3_A: DRV8714S-Q1 (U27.4), AM263P PRU_EPWM (R220.1)
EPWM3_B: DRV8714S-Q1 (U27.5), AM263P PRU_EPWM (R224.1)
EPWM4_A: DRV8714S-Q1 (U27.6), AM263P PRU_EPWM (R227.1)
EPWM4_B: DRV8714S-Q1 (U27.7), AM263P PRU_EPWM (R229.1)
EPWM5_A: Input Supply (R27.1 U1.12), AM263P PRU_EPWM (U32.F2)
EPWM5_B: MUXes and TPLD (U51.20), AM263P PRU_EPWM (U32.G2)
EPWM6_A: CAN-LIN Overview (D54.1), CAN1 (U5.8), AM263P PRU_EPWM (U32.E1)
EPWM6_B: AM263P PRU_EPWM (U32.F3), Ethernet (J13.20)
EPWM7_B: AM263P Overview (R365.2), AM263P PRU_EPWM (U32.F1)
EPWM8_A: AM263P Overview (R366.2), AM263P PRU_EPWM (U32.G3)
EPWM9_A: MUXes and TPLD (U50.6), AM263P PRU_EPWM (U32.G1)
EPWM10_A: AM263P Overview (R362.2), AM263P PRU_EPWM (U32.G4)
EPWM_13A: AM263P Overview (R361.2), AM263P PRU_EPWM (U32.K4)
EPWM_14A: AM263P PRU_EPWM (U32.V17), Ethernet (J12.20)
EPWM_14B: AM263P PRU_EPWM (U32.T16), Ethernet (J11.23 J12.24 J13.24)
EPWM_15A: Zone Reference Design Top Sheet (R478.1), TPS1214-Q1 (R479.1), AM263P PRU_EPWM (U32.P15)
EQEP0_A: Input Supply (R26.1 U1.7), AM263P PRU_EPWM (U32.B14)
EQEP0_B: MUXes and TPLD (U51.22), AM263P PRU_EPWM (U32.A14)
EQEP0_STROBE: MUXes and TPLD (U48.6), AM263P PRU_EPWM (U32.C12)
EXT_VMON1: PMIC (U41.16), BUCKs and LDO (R405.1 R410.2)
EXT_VMON2: PMIC (U41.10), BUCKs and LDO (R414.1 R416.2)
FETGOOD: Input Supply (R35.1 U4.3), MUXes and TPLD (U52.6)
FG_LM74704_MCU: MUXes and TPLD (U52.18), AM263P PRU_EPWM (U32.D9)
FLT/: Load Driver Overview (R10.2), TPS1214-Q1 (R468.1 U56.6), IO Expanders (U55.8)
FLT_I_TPS1211: TPS1211-Q1 (R378.2 U42.5), IO Expanders (U54.22)
FLT_T_TPS1211: Load Driver Overview (R14.2), TPS1211-Q1 (R380.2 U42.4), IO Expanders (U54.23)
FLT_TPS2HCS05: Load Driver Overview (R4.2), Smart Fuse HSS (R102.2), MUXes and TPLD (U49.7), IO Expanders (U55.5)
FLT_TPS2HCS10/08: Load Driver Overview (R7.2), Smart Fuse HSS (R86.1), MUXes and TPLD (U49.6), IO Expanders (U55.6)
GPI2: Power Overview (SW6.1), PMIC (U41.21)
GPI5: Power Overview (SW7.1), PMIC (U41.28)
GPIO14: MUXes and TPLD (U52.19), AM263P PRU_EPWM (U32.B11)
GPIO75: AM263P PRU_EPWM (U32.L3), Ethernet (J11.19)
GPIO79: TPS1214-Q1 (U56.3), AM263P PRU_EPWM (U32.B5)
GPIO81: IO Expanders (R446.2 U54.32), AM263P PRU_EPWM (U32.A3)
GPIO85: CAN1 (U5.14), AM263P PRU_EPWM (U32.L17)
GPIO86: CAN1 (U6.8), CAN2 (U7.8 U7.14), AM263P PRU_EPWM (U32.L18)
GPIO107: TPS1214-Q1 (U56.2), AM263P PRU_EPWM (U32.E16)
GPIO112: MUXes and TPLD (U50.3), AM263P PRU_EPWM (U32.E18)
GPIO124: MUXes and TPLD (U50.4), AM263P PRU_EPWM (U32.A16)
GPIO125: CAN2 (U8.1), AM263P PRU_EPWM (U32.D13)
GPO2: Power Overview (R344.2), PMIC (U41.23)
GPO3: Power Overview (R345.2), PMIC (U41.26)
I2C0_SCL: IO Expanders (U55.19), AM263P Overview (J15.2 J20.12), AM263P Temp and EEPROM (U36.8 U37.6), AM263P PRU_EPWM (R221.1 U32.A13), Class-D Amp (U43.33)
I2C0_SDA: IO Expanders (U55.20), AM263P Overview (J15.3 J20.11), AM263P Temp and EEPROM (U36.7 U37.5), AM263P PRU_EPWM (R222.1 U32.B13), Class-D Amp (U43.34)
I2C1_SDA: AM263P Overview (R363.2), AM263P PRU_EPWM (U32.C8)
I2S_FSYNC_ETH_MCU: AM263P PRU_EPWM (U32.G15), Ethernet (R78.2 U18.4)
I2S_SCLK_ETH_MCU: AM263P PRU_EPWM (U32.G17), Ethernet (U15.4)
IMON: TPS1214-Q1 (C403.1 R473.2 U56.9), AM263P ADC (R308.1)
IN0_MSDI: IO Management (J29.C1), TIC12400-Q1 (C133.2 R180.1)
IN1_MSDI: IO Management (J29.B1), TIC12400-Q1 (C134.2 R181.1)
IN2_MSDI: IO Management (J29.B15), TIC12400-Q1 (C137.2 R183.1)
IN3_MSDI: IO Management (J29.C16), TIC12400-Q1 (C138.2 R184.1)
IN4_MSDI: IO Management (J29.C15), TIC12400-Q1 (C140.2 R186.1)
IN5_MSDI: IO Management (J29.C14), TIC12400-Q1 (C141.2 R188.1)
IN6_MSDI: IO Management (J29.B13), TIC12400-Q1 (C142.2 R189.1)
IN7_MSDI: IO Management (J29.C13), TIC12400-Q1 (C143.2 R190.1)
IN8_MSDI: IO Management (J29.C12), TIC12400-Q1 (C144.2 R192.1)
IN9_MSDI: IO Management (J29.B11), TIC12400-Q1 (C146.2 R193.1)
IN10_MSDI: IO Management (J29.C11), TIC12400-Q1 (C149.2 R194.1)
IN11_MSDI: IO Management (J29.C10), TIC12400-Q1 (C151.2 R195.1)
IN12_MSDI: IO Management (J29.B9), TIC12400-Q1 (C153.2 R196.1)
IN13_MSDI: IO Management (J29.C9), TIC12400-Q1 (C156.2 R197.1)
IN14_MSDI: IO Management (J29.C8), TIC12400-Q1 (C159.2 R199.1)
IN15_MSDI: IO Management (J29.C7), TIC12400-Q1 (C150.2 R198.1)
IN16_MSDI: IO Management (J29.B7), TIC12400-Q1 (C152.2 R200.1)
IN17_MSDI: IO Management (J29.C6), TIC12400-Q1 (C155.2 R201.1)
IN18_MSDI: IO Management (J29.C5), TIC12400-Q1 (C158.2 R202.1)
IN19_MSDI: IO Management (J29.B5), TIC12400-Q1 (C161.2 R203.1)
IN20_MSDI: IO Management (J29.C4), TIC12400-Q1 (C154.2 R204.1)
IN21_MSDI: IO Management (J29.C3), TIC12400-Q1 (C157.2 R205.1)
IN22_MSDI: IO Management (J29.B3), TIC12400-Q1 (C160.2 R206.1)
IN23_MSDI: IO Management (J29.C2), TIC12400-Q1 (C162.2 R207.1)
INH_ETH: Zone Reference Design Top Sheet (D40.2), Ethernet (J11.12 J12.36 J13.36)
INH_TCAN1043A: PMIC (R335.1 U41.6), LIN (U10.8), CAN1 (R39.1 R41.2)
INP_G_TPS1211: TPS1211-Q1 (U42.2), IO Expanders (U54.24)
INP_TPS1211: TPS1211-Q1 (U42.3), IO Expanders (U54.25)
INT_MSDI: MUXes and TPLD (U49.3 U51.2), TIC12400-Q1 (D19.2 R182.2)
ITMPO: TPS1214-Q1 (C402.1 R470.1 U56.10), AM263P ADC (R312.1)
LATCH_TPS1HC30: High Side Switches (R118.1), IO Expanders (U54.11)
LHI_HCS: PMIC (R337.1 U41.27), Smart Fuse HSS (R83.2 R95.2 R99.2)
LIN0_RXD: LIN (R73.1 U11.10), AM263P PRU_EPWM (U32.B6)
LIN0_TXD: LIN (U11.12), AM263P PRU_EPWM (U32.A4)
LIN1_RXD: LIN (R65.1 U10.1), AM263P PRU_EPWM (U32.A9)
LIN1_TXD: LIN (U10.4), AM263P PRU_EPWM (U32.B9)
LIN2_RXD: LIN (R69.1 U11.1), AM263P PRU_EPWM (U32.B8)
LIN2_TXD: LIN (U11.3), AM263P PRU_EPWM (U32.A8)
LIN3_RXD: LIN (R71.1 U11.4), AM263P PRU_EPWM (U32.C11)
LIN4_RXD: LIN (R72.1 U11.7), AM263P PRU_EPWM (U32.A10)
LIN4_TXD: LIN (U11.9), AM263P PRU_EPWM (U32.C9)
LPM_TPS4HC120: High Side Switches (R146.1), MUXes and TPLD (U49.4), IO Expanders (U55.4)
MCU_INTn: AM263P Reset Circuit (R327.2 U40.5), AM263P PRU_EPWM (U32.D14)
MCU_PORz: MUXes and TPLD (U50.1 U53.2), AM263P Reset Circuit (R477.1 TP7.1 U32.R2 U39.4), AM263P OSPI Bootmode (R292.1 U34.2)
MCU_WARMRSTn: MUXes and TPLD (U50.2), AM263P Reset Circuit (R330.2 U32.C3 U40.2), AM263P OSPI Bootmode (R293.1)
MDC_ETH: AM263P PRU_EPWM (R239.1 U32.M17), Ethernet (J11.24 J12.48 J13.48)
MDIO_ETH: AM263P PRU_EPWM (R238.1 U32.N16), Ethernet (J11.26 J12.50 J13.50)
nCS: DRV8x45S-Q1 and DRV81242-Q1 (R167.2 U28.13 U29.13), AM263P Overview (J17.7), AM263P PRU_EPWM (U32.K2)
nFAULT_DRV8145: Load Driver Overview (R6.2 R9.2), DRV8x45S-Q1 and DRV81242-Q1 (R165.1 R166.1 U28.1 U29.1), IO Expanders (U54.9)
nFAULT_TPS1HC04: Load Driver Overview (R13.2), High Side Switches (R137.2), IO Expanders (U54.19)
nFAULT_TPS1HC30: Load Driver Overview (R5.2), High Side Switches (R121.1), IO Expanders (U54.20)
nFAULT_TPS2HC08: Load Driver Overview (R11.2), High Side Switches (R125.2), IO Expanders (U54.16)
nFAULT_TPS4HC120: Load Driver Overview (R8.2), High Side Switches (R145.1), IO Expanders (U55.17)
nFLT_DRV8714: Load Driver Overview (R12.2), DRV8714S-Q1 (R155.2 U27.9), IO Expanders (U54.26)
nINT_TCAL9539: MUXes and TPLD (U51.4), IO Expanders (R451.2 U55.22)
nSLEEP_DRV81242: DRV8714S-Q1 (U27.8), DRV8x45S-Q1 and DRV81242-Q1 (R172.1 U28.3 U29.3), IO Expanders (U54.7)
OA3_ED/SPI_CS_ETH3: AM263P Overview (J16.6), AM263P PRU_EPWM (U32.F18), Ethernet (J11.11)
OA3_RX_ETH3: AM263P PRU_EPWM (U32.G16), Ethernet (J11.13)
OA3_TX_ETH3: AM263P PRU_EPWM (U32.E17), Ethernet (J11.15)
OSPI0_D4: AM263P OSPI Bootmode (R257.1 R270.2), AM263P PRU_EPWM (U32.M1)
OSPI0_D5: AM263P OSPI Bootmode (R256.1 R271.2), AM263P PRU_EPWM (U32.L1)
OSPI0_D6: AM263P OSPI Bootmode (R255.1 R272.2), AM263P PRU_EPWM (U32.L2)
OSPI0_D7: AM263P OSPI Bootmode (R254.1 R273.2), AM263P PRU_EPWM (U32.K1)
OSPI0_DQS: AM263P OSPI Bootmode (R263.1 R274.2 R275.2), AM263P PRU_EPWM (U32.M3)
OSPI0_ECS: AM263P OSPI Bootmode (R265.1 U33.A5), AM263P PRU_EPWM (U32.H1)
OSPI0_RESET_OUTn: AM263P OSPI Bootmode (R277.1 U34.1), AM263P PRU_EPWM (U32.J1)
OUT0_LS_DRV81242: Load Driver Overview (J6.5), DRV8x45S-Q1 and DRV81242-Q1 (C125.1 U30.6)
OUT1_DRV8145: Load Driver Overview (J4.1), DRV8x45S-Q1 and DRV81242-Q1 (5 pins)
OUT1_DRV8245: Load Driver Overview (J2.2), DRV8x45S-Q1 and DRV81242-Q1 (C115.2 U28.8 U28.9)
OUT1_DRV8714: Load Driver Overview (J7.1), DRV8714S-Q1 (10 pins)
OUT1_LS_DRV81242: Load Driver Overview (J6.4), DRV8x45S-Q1 and DRV81242-Q1 (C126.1 U30.19)
OUT1_TLIN1024A: CAN-LIN Overview (J25.3), LIN (C50.1 R66.1 U11.22)
OUT1_TPS2HC08: Load Driver Overview (J10.2), High Side Switches (C76.1 U24.1)
OUT1_TPS4HC120: Load Driver Overview (J9.4), High Side Switches (C85.1 U25.27 U25.28)
OUT2_DRV8245: Load Driver Overview (J2.1), DRV8x45S-Q1 and DRV81242-Q1 (C119.2 U28.5 U28.6)
OUT2_DRV8714: Load Driver Overview (J7.2), DRV8714S-Q1 (C107.1 NT1.1 R154.2)
OUT2_LS_DRV81242: Load Driver Overview (J6.6), DRV8x45S-Q1 and DRV81242-Q1 (C127.1 U30.7)
OUT2_TLIN1024A: CAN-LIN Overview (J25.5), LIN (C51.1 R67.1 U11.20)
OUT2_TPS2HC08: Load Driver Overview (J10.1), High Side Switches (C81.1 U24.11)
OUT2_TPS4HC120: Load Driver Overview (J9.3), High Side Switches (C91.1 U25.25 U25.26)
OUT3_DRV8714: Load Driver Overview (J8.1), DRV8714S-Q1 (10 pins)
OUT3_HS_DRV81242: Load Driver Overview (J6.3), DRV8x45S-Q1 and DRV81242-Q1 (C128.1 U30.17)
OUT3_TLIN1024A: CAN-LIN Overview (J25.7), LIN (C52.1 R68.1 U11.17)
OUT3_TPS4HC120: Load Driver Overview (J9.2), High Side Switches (C93.1 U25.17 U25.18)
OUT4__HS_DRV81242: Load Driver Overview (J6.7), DRV8x45S-Q1 and DRV81242-Q1 (C129.1 U30.10)
OUT4_DRV8714: Load Driver Overview (J8.2), DRV8714S-Q1 (C111.1 NT4.1 R162.2)
OUT4_TLIN1024A: CAN-LIN Overview (J25.9), LIN (C53.1 R70.1 U11.15)
OUT4_TPS4HC120: Load Driver Overview (J9.1), High Side Switches (C94.1 U25.15 U25.16)
OUT5_HS_DRV81242: Load Driver Overview (J6.2), DRV8x45S-Q1 and DRV81242-Q1 (C130.1 U30.15)
OUT6_HS_DRV81242: Load Driver Overview (J6.8), DRV8x45S-Q1 and DRV81242-Q1 (C131.1 U30.11)
OUT7_HS_DRV81242: Load Driver Overview (J6.1), DRV8x45S-Q1 and DRV81242-Q1 (C132.1 U30.14)
OUT_TLIN1021A: CAN-LIN Overview (J25.1), LIN (C47.1 R64.1 U10.6)
OUT_TPS1HC04: Load Driver Overview (T3.1), High Side Switches (C86.1 U26.1 U26.11)
P15_TCAL9539: High Side Switches (R140.1), IO Expanders (U55.15)
P16_TCAL9539: High Side Switches (R144.1), IO Expanders (U55.16)
P23_TXE8116: High Side Switches (R120.1), IO Expanders (U54.14)
PMIC_DIAG: PMIC (U41.32), MUXes and TPLD (U52.5)
PMIC_EN_OUT: PMIC (U41.17), BUCKs and LDO (R404.1 R413.1)
PMIC_nINT: PMIC (R476.2), MUXes and TPLD (U52.4)
PMIC_nRST: PMIC (U41.13), AM263P Reset Circuit (R322.1)
PR0_PRU0_GPIO0: AM263P PRU_EPWM (R223.1), Ethernet (U19.12)
PR0_PRU0_GPIO1: AM263P PRU_EPWM (R225.1), Ethernet (U19.13)
PR0_PRU0_GPIO2: AM263P PRU_EPWM (R226.1), Ethernet (U19.14)
PR0_PRU0_GPIO3: AM263P PRU_EPWM (R228.1), Ethernet (U19.15)
PR0_PRU0_GPIO6: AM263P PRU_EPWM (R231.1), Ethernet (U19.10)
PR0_PRU0_GPIO11: AM263P PRU_EPWM (R232.1), Ethernet (U16.2)
PR0_PRU0_GPIO12: AM263P PRU_EPWM (R233.1), Ethernet (U16.3)
PR0_PRU0_GPIO13: AM263P PRU_EPWM (R234.1), Ethernet (U16.4)
PR0_PRU0_GPIO14: AM263P PRU_EPWM (R235.1), Ethernet (U16.5)
PR0_PRU0_GPIO15: AM263P PRU_EPWM (R236.1), Ethernet (U16.6)
PR0_PRU0_GPIO16: AM263P PRU_EPWM (R237.1), Ethernet (U16.7)
PR0_PRU1_GPIO8: AM263P Overview (J16.4), AM263P PRU_EPWM (U32.D18), Ethernet (J11.5)
PR0_PRU1_GPIO9: AM263P Overview (R359.2), AM263P PRU_EPWM (U32.C18)
PR0_PRU1_GPIO10: AM263P Overview (R360.2), AM263P PRU_EPWM (U32.D17)
PR0_PRU1_GPIO18: CAN2 (U8.2), AM263P Overview (J22.3), AM263P PRU_EPWM (U32.C15)
PR0_PRU1_GPIO19: CAN2 (U8.5), AM263P Overview (J22.2), AM263P PRU_EPWM (U32.D15)
PWM_ETH: Zone Reference Design Top Sheet (R478.2), AM263P PRU_EPWM (U32.R16), Ethernet (J12.28 J13.28)
RESET_ETH: IO Expanders (U55.1), Ethernet (J11.21 J12.22 J13.22)
RESET_MSDI: MUXes and TPLD (U50.7), TIC12400-Q1 (R191.1 U31.21)
RESET_TCAL: MUXes and TPLD (U51.6), IO Expanders (R450.2 U55.24)
RESET_TPS: BUCKs and LDO (Q22.1 R400.1 U44.4), MUXes and TPLD (R442.2)
RESET_TXE: MUXes and TPLD (U50.9), IO Expanders (R448.2 U54.31)
RGMII1_RD0: AM263P PRU_EPWM (R241.2), Ethernet (U13.12)
RGMII1_RD1: AM263P PRU_EPWM (R242.2), Ethernet (U13.13)
RGMII1_RD2: AM263P PRU_EPWM (R243.2), Ethernet (U13.14)
RGMII1_RD3: AM263P PRU_EPWM (R244.2), Ethernet (U13.15)
RGMII1_RXC: AM263P PRU_EPWM (R246.2), Ethernet (U13.10)
RGMII1_TD0: AM263P PRU_EPWM (R247.2), Ethernet (U12.2)
RGMII1_TD1: AM263P PRU_EPWM (R248.2), Ethernet (U12.3)
RGMII1_TD2: AM263P PRU_EPWM (R249.2), Ethernet (U12.4)
RGMII1_TD3: AM263P PRU_EPWM (R250.2), Ethernet (U12.5)
RGMII1_TX_CTL: AM263P PRU_EPWM (R251.2), Ethernet (U12.6)
RGMII1_TXC: AM263P PRU_EPWM (R252.2), Ethernet (U12.7)
RXD2_TCAN1046_UART: CAN2 (U8.13), AM263P Overview (J21.2), AM263P PRU_EPWM (U32.C13)
S0_TMUX1308: IO Management (J28.8), MUXes and TPLD (C374.2 R426.1)
S1_TMUX1308: IO Management (J28.7), MUXes and TPLD (C375.2 R427.1)
S2_TMUX1308: IO Management (J28.6), MUXes and TPLD (C376.2 R428.1)
S3_TMUX1308: IO Management (J28.5), MUXes and TPLD (C377.2 R429.1)
S4_TMUX1308: IO Management (J28.4), MUXes and TPLD (C378.2 R430.1)
S5_TMUX1308: IO Management (J28.3), MUXes and TPLD (C379.2 R431.1)
S6_TMUX1308: IO Management (J28.2), MUXes and TPLD (C380.2 R432.1)
S7_TMUX1308: IO Management (J28.1), MUXes and TPLD (C381.2 R433.1)
SAFE_OUT1: Power Overview (Q15.1), PMIC (R341.2)
SAFETY_ERRORn: Power Overview (Q16.1), PMIC (U41.18), AM263P Reset Circuit (U32.D4)
SCLK: DRV8714S-Q1 (U27.1), DRV8x45S-Q1 and DRV81242-Q1 (R175.1 U28.14 U29.14), Smart Fuse HSS (R85.1 R110.1), AM263P Overview (J17.4 R361.1)
SCLK_IO: TIC12400-Q1 (U31.16), IO Expanders (U54.29), AM263P Overview (J19.2 J20.13 R365.1)
SCLK_PMIC: PMIC (U41.33), AM263P Overview (J18.2 R363.1)
SDFM_CLK2: CAN2 (U8.11), AM263P Overview (J21.3), AM263P PRU_EPWM (U32.B15)
SDI: DRV8714S-Q1 (U27.2), DRV8x45S-Q1 and DRV81242-Q1 (R176.1 U28.15), Smart Fuse HSS (R88.1 R104.1), AM263P Overview (J17.6 R362.1)
SDI_IO: TIC12400-Q1 (U31.17), IO Expanders (U54.30), AM263P Overview (J19.3 J20.14 R366.1)
SDI_PMIC: PMIC (U41.35), AM263P Overview (J18.3 R364.1)
SDO_IO: TIC12400-Q1 (R187.2), IO Expanders (R449.1), AM263P Overview (J19.4 R367.1), AM263P PRU_EPWM (U32.H2)
SDO_LD: DRV8714S-Q1 (R159.1), DRV8x45S-Q1 and DRV81242-Q1 (R170.1 R177.1), Smart Fuse HSS (R98.1 R105.1), AM263P Overview (J17.8), AM263P PRU_EPWM (U32.J3)
SDO_PMIC: PMIC (R340.1), AM263P Overview (J18.4), AM263P PRU_EPWM (U32.C7)
SPI0_CLK: LIN (U11.6), AM263P OSPI Bootmode (R286.1), AM263P PRU_EPWM (U32.A11)
SPI0_D0: MUXes and TPLD (U52.20), AM263P OSPI Bootmode (R287.1), AM263P PRU_EPWM (U32.C10)
SPI5_CLK: AM263P Overview (J16.2 R359.1), Ethernet (J11.7)
SPI5_SDI: AM263P Overview (J16.3 R360.1), Ethernet (J11.3)
SPI6_CS3: AM263P Overview (J20.16), AM263P PRU_EPWM (U32.D11)
SPI7_CS2: MUXes and TPLD (U51.16), AM263P Overview (J17.9), AM263P OSPI Bootmode (R262.1)
SPI7_CS5: DRV8714S-Q1 (R158.2 U27.56), AM263P Overview (J17.3), AM263P Reset Circuit (U32.P2)
SRC: Load Driver Overview (T1.1), TPS1214-Q1 (11 pins)
TCLK: AM263P Overview (J20.4), AM263P PRU_EPWM (U32.B3)
TDI: AM263P Overview (J20.5), AM263P PRU_EPWM (U32.C5)
TDO: AM263P Overview (J20.6), AM263P PRU_EPWM (R240.1)
TMS: AM263P Overview (J20.3), AM263P PRU_EPWM (U32.D5)
UART0_CTS: AM263P Overview (R364.2), AM263P PRU_EPWM (U32.B7)
UART0_RX: AM263P Overview (J20.9), AM263P PRU_EPWM (U32.A7)
UART0_TX: AM263P Overview (J20.10), AM263P PRU_EPWM (U32.A6)
VOUT1_TPS2HCS05: Load Driver Overview (J1.1), Smart Fuse HSS (C70.1 U22.7 U22.8)
VOUT1_TPS2HCS08: Load Driver Overview (J5.1), Smart Fuse HSS (C65.1 U21.6 U21.7 U21.8)
VOUT1_TPS2HCS10: Load Driver Overview (J3.1), Smart Fuse HSS (C59.1 U20.6 U20.7 U20.8)
VOUT2_TPS2HCS05: Load Driver Overview (J1.2), Smart Fuse HSS (C72.1 U22.11 U22.12)
VOUT2_TPS2HCS08: Load Driver Overview (J5.2), Smart Fuse HSS (C68.1 U21.9 U21.10 U21.11)
VOUT2_TPS2HCS10: Load Driver Overview (J3.2), Smart Fuse HSS (C62.1 U20.9 U20.10 U20.11)
VOUT_TPS1HC30: Load Driver Overview (J4.2), High Side Switches (C82.1 U23.9 U23.10)
VOUT_TPS1211: Load Driver Overview (T2.1), TPS1211-Q1 (9 pins)
WAKE: TPS1214-Q1 (C400.1 R469.1 U56.5), MUXes and TPLD (U49.9), IO Expanders (U55.3)
WAKE2: Zone Reference Design Top Sheet (D40.1), Power Overview (D41.1), PMIC (R336.1 U41.43), MUXes and TPLD (D55.1)

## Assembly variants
001: not fitted C116 C117 C385 C386 D57 FID1 FID2 FID3 R36 R77 R78 R79 R326 R327 R328 R391 R479; alternate parts R24 -> CMP-0022129-4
